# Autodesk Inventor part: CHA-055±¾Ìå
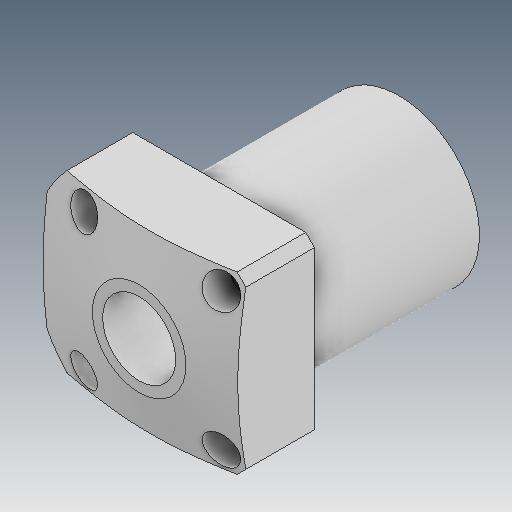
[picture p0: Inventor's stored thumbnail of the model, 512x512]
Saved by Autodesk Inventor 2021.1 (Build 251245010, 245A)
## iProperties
Created: 2019-05
Part Number: CHA-055±¾Ìå
Material: Ogólny
Document SubType Name: Modeling
Designer: user
Density: 1 g/cm^3
Appearance: Domyślna
Author: user
Revision Number: ÈÎºÎ
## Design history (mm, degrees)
feature "ÊäÈë1"
node "Bryła1"
